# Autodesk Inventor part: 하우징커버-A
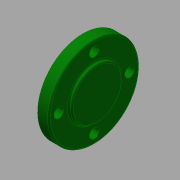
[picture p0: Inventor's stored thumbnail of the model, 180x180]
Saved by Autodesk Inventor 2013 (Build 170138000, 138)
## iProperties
Created: 2018-01
Part Number: 하우징커버-A
Material: 알루미늄 6061
Document SubType Name: Modeling
Designer: mduedu
Density: 1 g/cm^3
Author: mduedu
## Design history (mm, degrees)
sketch "스케치1"
  geometry: C1 r 16 at (0, 0); 1 further point
  constraints: 1 centre point, 1 coincident
  dimensions: "d0" = 32 diameter of C1
extrude "돌출1" new body sketch "스케치1" distance "d1" = 4; taper "d2" = 0 deg
sketch "스케치2"
  geometry: C1 r 9 at (0, 0); 1 further point
  constraints: 1 centre point, 1 coincident
  dimensions: "d3" = 18 diameter of C1
extrude "돌출2" join sketch "스케치2" distance "d4" = 1; taper "d5" = 0 deg
fillet "모깎기1" dims "d6" = 0.5
fillet "모깎기2" dims "d7" = 0.5
sketch "스케치3" dims "d8" = 25
  geometry: 6 further points
  constraints: 2 vertical alignment, 1 coincident, 7 other
  dimensions: "d11" = 360 deg dimension on point (0, 0) point (0, 12.5) (derived)
sketch "스케치4"
  geometry: 4 further points
  constraints: 4 other
hole "구멍1" sketch "스케치4" at (-12.5, 0), (0, -12.5), (12.5, 0), (0, 12.5) diameter "d13" = 3.4; stored, may be unused: countersink angle "d17" = 90 deg, drill point angle "d19" = 0 deg; dims "d14" = 6, "d15" = 4, "d16" = 2, "d18" = 8
node "솔리드1"
